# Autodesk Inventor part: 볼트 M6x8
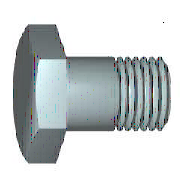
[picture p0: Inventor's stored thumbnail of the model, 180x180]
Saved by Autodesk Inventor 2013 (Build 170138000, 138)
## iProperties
Created: 2012-02
Part Number: 볼트 M6x8
Material: 강철, 연강
Description: 6각 머리 볼트 및 6각 머리 나사
Document SubType Name: Modeling
Standard: KS B 1002
Designer: mduedu
Standards Organization: KS
Language: ko-KR
Size Designation: C  M 6 x 12
Categories: <MemberInstance><Categories><Category DisplayName="조임쇠" InternalName="e4da775c-781d-43d5-af7c-5136215cf5a6" Mnemonic="FSTN"><Category DisplayName="볼트" InternalN
Density: 1 g/cm^3
IsCustomPart: 1
Author: mduedu
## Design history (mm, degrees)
sketch "스케치1"
  geometry: L1 (0, 3)-(8, 3); L2 (8, 3)-(8, 0); L3 (8, 0)-(0, 0); L4 (-2.4, 0)-(14.4, 0) reference; L5 (0, -0.6)-(0, 3.6) reference; L6 (0, 3)-(0, 0)
  constraints: 8 end point, 3 point on line, 1 collinear
  dimensions: "d2" = 6 diameter of L1 L3 (= GD); "d59" = 8 distance between parallel lines of L2 L5 (= NLG)
revolve "본체" sketch "스케치1" stored, may be unused: angle "d12" = 90 deg
sketch "스케치2"
  geometry: L1 (0, 5.774)-(5, 2.887); L2 (5, 2.887)-(5, -2.887); L3 (5, -2.887)-(0, -5.774); L4 (0, -5.774)-(-5, -2.887); L5 (-5, -2.887)-(-5, 2.887); L6 (-5, 2.887)-(0, 5.774); L7 (-7, 0)-(7, 0) reference; L8 (0, 8.083)-(0, -8.083) reference; 2 further points
  constraints: 12 end point, 2 midpoint, 1 coincident, 1 vertical, 11 other
  dimensions: "d11" = 10 distance between parallel lines of L5 L2 (= SW)
extrude "머리" join sketch "스케치2" distance "d3" = 4 (= KOH); taper "d4" = 0 deg
revolve "모따기1" stored, may be unused: angle "d21" = 90 deg
workplane "Work Plane1"
body "Solid1"
feature "스레드" dims "d15" = 9 (= GEL), "d16" = 0
chamfer "모따기2" distance "d6" = 0.61345 (= -0.5 x SPD + 0.5 x GD); stored, may be unused: second distance "d7" = 0.61355 (computed from GUL), angle "d55" = 45 deg
sketch "스케치4"
  geometry: L1 (-3.423, 6)-(-4, 5); L2 (-1.1, 0)-(-0.234, 0); L3 (-4.753, 0)-(0.519, 0) reference; L4 (-4, 6)-(-3.423, 6); L5 (-4, 5)-(-4, 6); L6 (0, 7.2)-(0, -1.2) reference
  constraints: 8 end point, 1 parallel, 1 perpendicular, 1 point on line
  dimensions: "d65" = 10 diameter of L1.end L2 (= SW); "d67" = 30 deg angle of L1 L5 (= ANG1); "d68" = 12 diameter of L4 L2 (= 1.2 x SW); "d69" = 4 distance between parallel lines of L5 L6 (= KOH)
other parameters: "NLG" = 8 [user parameter; used in 1 equation term], "GD" = 6 (= NND) [user parameter; used in 2 equation terms], "BDM" = 6 (= NND) [user parameter], "KOH" = 4 [user parameter; used in 2 equation terms], "GEL" = 9 [user parameter; used in 1 equation term], "SW" = 10 [user parameter; used in 5 equation terms], "SPD" = 4.7731 (= NND - 1.2269 x PTC) [user parameter; used in 1 equation term], "SD2" = 6 (= NND) [user parameter], "SD" = 0 [user parameter], "ANG1" = 30 deg [user parameter; used in 1 equation term], "GAL" = 0.61345 (= 0.61345 x PTC) [user parameter], "GUL" = 0.61345 (= 0.61345 x PTC) [user parameter; used in 1 equation term], "d8" = 0, "RR" = 0.25 [user parameter], "d58" = 0, "RR1" = 0.1 [user parameter], "GD1" = 4.7731 (= THREADDIA - 1.2269 x PTC) [user parameter], "THREADDIA" = 6 [user parameter; used in 1 equation term], "TOA" = 30 deg [user parameter], "PTC" = 1 [user parameter; used in 5 equation terms], "NND" = 6 [user parameter; used in 4 equation terms], "E0" = 11.55 (= 1.155 x SW) [user parameter]
